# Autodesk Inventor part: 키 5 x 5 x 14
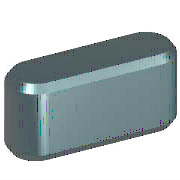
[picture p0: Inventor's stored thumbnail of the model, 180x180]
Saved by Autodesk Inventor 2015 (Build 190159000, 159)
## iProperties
IsCustomPart: 1
Created: 2012-02
Part Number: 키 5 x 5 x 14
Material: 강철, 연강
Description: 키 및 해당 키홈
Document SubType Name: Modeling
Standard: KS B 1311
Designer: mduedu
Standards Organization: KS
Language: ko-KR
Size Designation: 5 x 5 x 14
Categories: <MemberInstance><Categories><Category DisplayName="샤프트 부품" InternalName="7f7aeb1f-a693-4053-b835-cee3144e0d98" Mnemonic="SHFT"><Category DisplayName="키" Interna
Density: 1 g/cm^3
Appearance: 노란색
Author: mduedu
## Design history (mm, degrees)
workplane "Work Plane1"
workplane "Work Plane2"
sketch "스케치1"
  geometry: L1 (2.5, 2.5)-(11.5, 2.5); L2 (11.5, -2.5)-(2.5, -2.5); L3 (0, 9.4)-(0, -7.4) reference; L4 (-5, 0)-(30, 0) reference; L5 (14, 0)-(14, 7); A1 r 2.5 centre (2.5, 0) between (2.5, 2.5) and (2.5, -2.5); A2 r 2.5 centre (11.5, 0) between (11.5, -2.5) and (11.5, 2.5)
  constraints: 6 end point, 5 point on circle, 4 tangent, 3 point on line, 2 centre point, 1 horizontal, 1 parallel, 1 perpendicular
  dimensions: "d0" = 2.5 radius of A1 (= 0.5 x PB); "d13" = 2.5 radius of A2 (= 0.5 x PB); "d14" = 14 distance between parallel lines of L5 L3 (= NLG)
extrude "본체1" new body sketch "스케치1" taper "d3" = 0 deg; stored distance "d4" = 10
workplane "Work Plane3"
body "Solid1"
chamfer "모따기1" distance "d8" = 0.4 (= PHH); stored, may be unused: second distance "d9" = 0.4 (= PHH), angle "d15" = 45 deg
other parameters: "d1" = -3 (= -PNT), "d2" = 2 (= PH - PNT), "NLG" = 14 [user parameter; used in 3 equation terms], "PB" = 5 [user parameter; used in 2 equation terms], "PNT" = 3 [user parameter; used in 2 equation terms], "PH" = 5 [user parameter; used in 1 equation term], "PHH" = 0.4 [user parameter; used in 2 equation terms], "d10" = 0, "d16" = 0, "d17" = 0, "d18" = 0, "WDMIN" = 12 [user parameter], "PLB2" = 14 (= NLG) [user parameter], "WDMAX" = 17 [user parameter], "PLB1" = 14 (= NLG) [user parameter], "RR" = 0.16 [user parameter], "PUEB" = 2.3 [user parameter]
